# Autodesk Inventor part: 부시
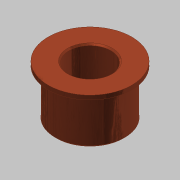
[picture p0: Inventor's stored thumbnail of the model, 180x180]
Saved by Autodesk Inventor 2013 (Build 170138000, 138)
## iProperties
Created: 2015-10
Part Number: 부시
Document SubType Name: Modeling
Designer: mdu
Density: 7.86 g/cm^3
Material: 강철, 연강
Mass: 374.583 g
Surface Area: 131.821 cm^2
Volume: 47.6569 cm^3
Author: mdu
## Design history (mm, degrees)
sketch "스케치1"
  geometry: C1 r 31 at (0, 0) reference; C2 r 25 at (0, 0) reference; C3 r 30 at (0, 0) reference; 1 further point
  node "참조1"
  node "참조2"
  node "참조4"
extrude "돌출1" new body sketch "스케치1" distance "d0" = 3; taper "d1" = 0 deg
extrude "돌출2" join sketch "스케치1" distance "d2" = 36; taper "d3" = 0 deg
chamfer "모따기1" distance "d6" = 1; stored, may be unused: second distance "d7" = 2, angle "d8" = 45 deg
sketch "스케치3"
  geometry: C1 r 15 at (0, 0); 1 further point
  constraints: 1 centre point, 1 coincident
  dimensions: "d13" = 30 diameter of C1
extrude "돌출4" cut sketch "스케치3" stored distance "d14" = 10; taper "d15" = 0 deg
chamfer "모따기3" distance "d16" = 1; stored, may be unused: second distance "d17" = 2, angle "d18" = 45 deg
node "솔리드1"
